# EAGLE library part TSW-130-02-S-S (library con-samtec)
THROUGH-HOLE .025" SQ POST HEADER Source: Samtec TSW.pdf
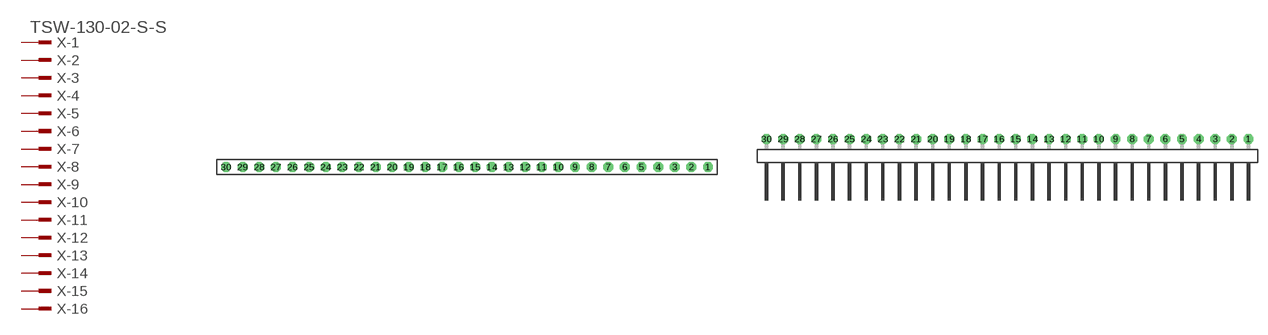
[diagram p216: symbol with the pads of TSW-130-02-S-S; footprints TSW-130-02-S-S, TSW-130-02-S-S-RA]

Designator prefix X; gates -1=MPINV -2=MPIN -3=MPIN -4=MPIN -5=MPIN -6=MPIN -7=MPIN -8=MPIN -9=MPIN -10=MPIN -11=MPIN -12=MPIN -13=MPIN -14=MPIN -15=MPIN -16=MPIN -17=MPIN -18=MPIN -19=MPIN -20=MPIN -21=MPIN -22=MPIN -23=MPIN -24=MPIN -25=MPIN -26=MPIN -27=MPIN -28=MPIN -29=MPIN -30=MPIN

## TSW-130-02-S-S (OC_FARNELL: unknown; OC_NEWARK: unknown)  [TSW-130-02-S-S]
1  -1:1  pas
2  -2:1  pas
3  -3:1  pas
4  -4:1  pas
5  -5:1  pas
6  -6:1  pas
7  -7:1  pas
8  -8:1  pas
9  -9:1  pas
10  -10:1  pas
11  -11:1  pas
12  -12:1  pas
13  -13:1  pas
14  -14:1  pas
15  -15:1  pas
16  -16:1  pas
17  -17:1  pas
18  -18:1  pas
19  -19:1  pas
20  -20:1  pas
21  -21:1  pas
22  -22:1  pas
23  -23:1  pas
24  -24:1  pas
25  -25:1  pas
26  -26:1  pas
27  -27:1  pas
28  -28:1  pas
29  -29:1  pas
30  -30:1  pas

## TSW-130-02-S-S-RA (OC_FARNELL: unknown; OC_NEWARK: unknown)  [TSW-130-02-S-S-RA]
Pads as for TSW-130-02-S-S

## Footprint TSW-130-02-S-S (pad centres in mm)
THROUGH-HOLE .025" SQ POST HEADER Source: Samtec TSW.pdf
drill 1 pad 1.5 octagon: 1 36.83,0; 2 34.29,0; 3 31.75,0; 4 29.21,0; 5 26.67,0; 6 24.13,0; 7 21.59,0; 8 19.05,0; 9 16.51,0; 10 13.97,0; 11 11.43,0; 12 8.89,0; 13 6.35,0; 14 3.81,0; 15 1.27,0; 16 -1.27,0; 17 -3.81,0; 18 -6.35,0; 19 -8.89,0; 20 -11.43,0; 21 -13.97,0; 22 -16.51,0; 23 -19.05,0; 24 -21.59,0; 25 -24.13,0; 26 -26.67,0; 27 -29.21,0; 28 -31.75,0; 29 -34.29,0; 30 -36.83,0

## Footprint TSW-130-02-S-S-RA (pad centres in mm)
THROUGH-HOLE .025" SQ POST HEADER Source: Samtec TSW.pdf
drill 1 pad 1.5 octagon: 1 36.83,1.524; 2 34.29,1.524; 3 31.75,1.524; 4 29.21,1.524; 5 26.67,1.524; 6 24.13,1.524; 7 21.59,1.524; 8 19.05,1.524; 9 16.51,1.524; 10 13.97,1.524; 11 11.43,1.524; 12 8.89,1.524; 13 6.35,1.524; 14 3.81,1.524; 15 1.27,1.524; 16 -1.27,1.524; 17 -3.81,1.524; 18 -6.35,1.524; 19 -8.89,1.524; 20 -11.43,1.524; 21 -13.97,1.524; 22 -16.51,1.524; 23 -19.05,1.524; 24 -21.59,1.524; 25 -24.13,1.524; 26 -26.67,1.524; 27 -29.21,1.524; 28 -31.75,1.524; 29 -34.29,1.524; 30 -36.83,1.524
